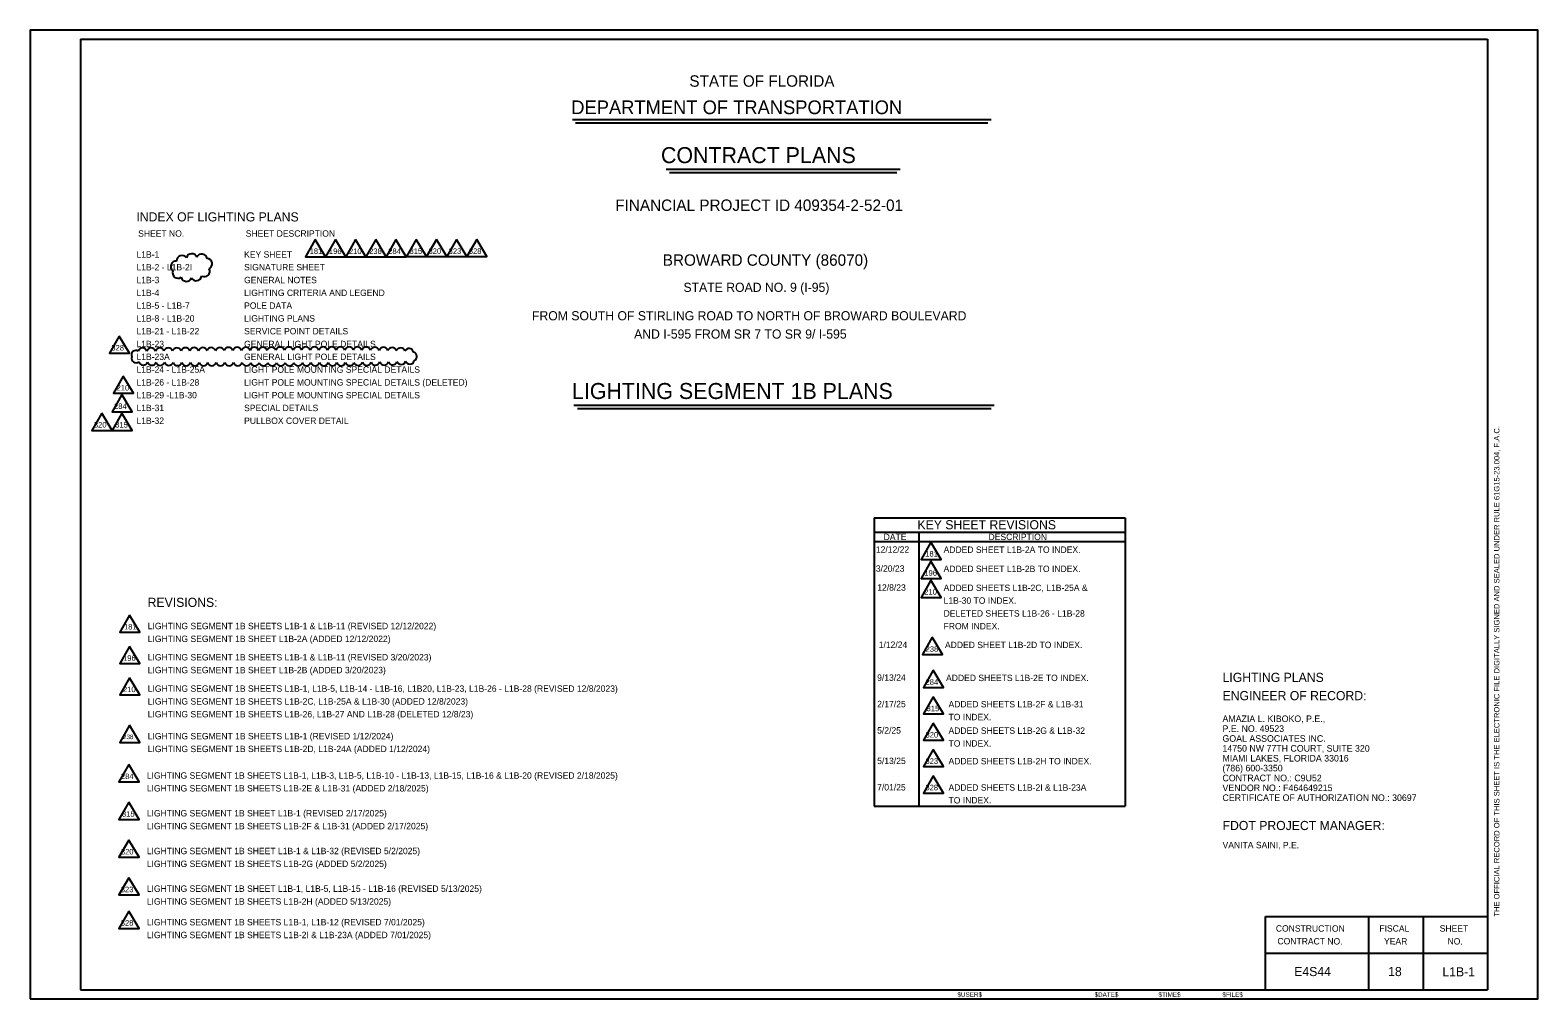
# Model space of a CAD drawing. Extents: x -818.6 to -802.1, y -2197.9 to -2175.
# Drawn here: x -818.56 to -802.06, y -2197.92 to -2187.32 of the extents above; entities that cross this region are included whole.
import ezdxf

# ---------------------------------------------------------------- set-up
doc = ezdxf.new("R2010")
doc.units = 0
for name, color, linetype in [('ActivePointCell_dp', 7, 'Continuous'), ('Cloud_dp', 7, 'Continuous'), ('PlotBorder_dp', 7, 'Continuous'), ('SheetBorder_dp', 7, 'Continuous'), ('SheetLines_dp', 7, 'Continuous'), ('SumBoxLines_dp', 7, 'Continuous'), ('TextLabel', 7, 'Continuous'), ('TextMinor', 7, 'Continuous'), ('TextMisc', 7, 'Continuous'), ('TextNotes', 7, 'Continuous'), ('TextShtNo', 7, 'Continuous'), ('TextTitle', 7, 'Continuous')]:
    doc.layers.add(name, color=color, linetype=linetype)

msp = doc.modelspace()

# ---------------------------------------------------------------- linework, layer by layer
at = {"layer": 'ActivePointCell_dp'}
msp.add_line((-802.614, -2187.419), (-802.614, -2187.419), dxfattribs=at)
at = {"layer": 'Cloud_dp'}
for points in [[(-815.443, -2189.61), (-815.551, -2189.798), (-815.33, -2189.798)], [(-815.222, -2189.61), (-815.33, -2189.798), (-815.109, -2189.798)], [(-815.002, -2189.61), (-815.109, -2189.798), (-814.889, -2189.798)], [(-814.781, -2189.61), (-814.889, -2189.798), (-814.668, -2189.798)], [(-814.56, -2189.61), (-814.667, -2189.798), (-814.447, -2189.798)], [(-814.339, -2189.609), (-814.446, -2189.797), (-814.226, -2189.797)], [(-814.118, -2189.609), (-814.226, -2189.797), (-814.005, -2189.797)], [(-813.897, -2189.609), (-814.005, -2189.797), (-813.784, -2189.797)], [(-813.677, -2189.609), (-813.784, -2189.797), (-813.564, -2189.797)], [(-817.588, -2190.666), (-817.696, -2190.854), (-817.475, -2190.854)], [(-817.545, -2191.104), (-817.652, -2191.292), (-817.432, -2191.292)], [(-817.559, -2191.306), (-817.667, -2191.494), (-817.446, -2191.494)], [(-817.78, -2191.509), (-817.888, -2191.698), (-817.667, -2191.698)], [(-817.559, -2191.509), (-817.667, -2191.698), (-817.446, -2191.698)], [(-808.706, -2192.922), (-808.814, -2193.11), (-808.593, -2193.11)], [(-808.706, -2193.13), (-808.814, -2193.318), (-808.593, -2193.318)], [(-808.706, -2193.338), (-808.814, -2193.526), (-808.593, -2193.526)], [(-817.475, -2193.719), (-817.583, -2193.907), (-817.362, -2193.907)], [(-808.691, -2193.963), (-808.799, -2194.151), (-808.578, -2194.151)], [(-817.475, -2194.062), (-817.583, -2194.25), (-817.362, -2194.25)], [(-808.68, -2194.324), (-808.787, -2194.512), (-808.567, -2194.512)], [(-817.475, -2194.405), (-817.583, -2194.593), (-817.362, -2194.593)], [(-808.68, -2194.613), (-808.787, -2194.801), (-808.567, -2194.801)], [(-817.475, -2194.924), (-817.583, -2195.113), (-817.362, -2195.113)], [(-808.68, -2194.901), (-808.787, -2195.089), (-808.567, -2195.089)], [(-808.68, -2195.19), (-808.787, -2195.378), (-808.567, -2195.378)], [(-817.485, -2195.356), (-817.593, -2195.544), (-817.372, -2195.544)], [(-808.68, -2195.478), (-808.787, -2195.667), (-808.567, -2195.667)], [(-817.485, -2195.768), (-817.593, -2195.957), (-817.372, -2195.957)], [(-817.485, -2196.181), (-817.593, -2196.369), (-817.372, -2196.369)], [(-817.485, -2196.594), (-817.593, -2196.782), (-817.372, -2196.782)], [(-817.485, -2196.96), (-817.593, -2197.148), (-817.372, -2197.148)]]:
    msp.add_lwpolyline(points, close=True, dxfattribs=at)
for centre, radius, start, end in [((-816.966, -2189.905), 0.0599, 86.9907, 231.9907), ((-816.902, -2189.845), 0.06, 35.4166, 180.4166), ((-816.795, -2189.825), 0.0599, 21.2778, 166.2778), ((-816.685, -2189.828), 0.0599, 9.9863, 154.9863), ((-816.632, -2189.877), 0.0599, 298.9542, 83.9542), ((-816.946, -2189.974), 0.0599, 159.4236, 304.4236), ((-816.854, -2190.008), 0.0599, 194.4381, 339.4381), ((-816.745, -2190.001), 0.0599, 207.5787, 352.5787), ((-816.657, -2189.957), 0.0599, 241.4449, 26.4449), ((-817.407, -2190.874), 0.0494, 58.9897, 203.9897), ((-817.334, -2190.846), 0.0494, 18.7741, 163.7741), ((-817.24, -2190.845), 0.0494, 17.5, 162.5), ((-817.146, -2190.845), 0.0494, 17.6778, 162.6778), ((-817.052, -2190.844), 0.0494, 17.8653, 162.8653), ((-816.958, -2190.844), 0.0494, 17.8653, 162.8653), ((-816.863, -2190.843), 0.0494, 17.8653, 162.8653), ((-816.769, -2190.842), 0.0494, 17.8653, 162.8653), ((-816.675, -2190.842), 0.0494, 17.8653, 162.8653), ((-816.581, -2190.841), 0.0494, 17.8653, 162.8653), ((-816.487, -2190.841), 0.0494, 17.8653, 162.8653), ((-816.393, -2190.84), 0.0494, 17.8653, 162.8653), ((-816.298, -2190.839), 0.0494, 17.8653, 162.8653), ((-816.204, -2190.839), 0.0494, 17.8653, 162.8653), ((-816.11, -2190.838), 0.0494, 17.8653, 162.8653), ((-816.016, -2190.838), 0.0494, 17.8653, 162.8653), ((-815.922, -2190.837), 0.0494, 17.8653, 162.8653), ((-815.828, -2190.836), 0.0494, 17.8653, 162.8653), ((-815.733, -2190.836), 0.0494, 17.8425, 162.8425), ((-815.639, -2190.835), 0.0494, 17.7853, 162.7853), ((-815.545, -2190.835), 0.0494, 17.7213, 162.7213), ((-815.451, -2190.835), 0.0494, 17.6494, 162.6494), ((-815.357, -2190.834), 0.0494, 17.5676, 162.5676), ((-815.263, -2190.834), 0.0494, 17.4736, 162.4736), ((-815.168, -2190.835), 0.0494, 17.3638, 162.3638), ((-815.074, -2190.835), 0.0494, 17.2336, 162.2336), ((-814.98, -2190.835), 0.0494, 17.0753, 162.0753), ((-814.886, -2190.836), 0.0494, 16.8775, 161.8775), ((-814.792, -2190.838), 0.0494, 16.6201, 161.6201), ((-814.698, -2190.839), 0.0494, 16.2655, 161.2655), ((-814.604, -2190.842), 0.0494, 15.7308, 160.7308), ((-814.51, -2190.845), 0.0494, 14.7785, 159.7785), ((-814.417, -2190.852), 0.0494, 12.0754, 157.0754), ((-814.38, -2190.89), 0.0493, 291.9354, 76.9354), ((-817.405, -2190.909), 0.0494, 163.0125, 308.0125), ((-817.327, -2190.935), 0.0494, 195.3369, 340.3369), ((-817.233, -2190.937), 0.0494, 196.5639, 341.5639), ((-817.139, -2190.939), 0.0494, 196.8661, 341.8661), ((-817.045, -2190.939), 0.0494, 197.0257, 342.0257), ((-816.951, -2190.94), 0.0494, 197.1286, 342.1286), ((-816.856, -2190.941), 0.0494, 197.2021, 342.2021), ((-816.762, -2190.941), 0.0494, 197.258, 342.258), ((-816.668, -2190.942), 0.0494, 197.3023, 342.3023), ((-816.574, -2190.942), 0.0494, 197.3386, 342.3386), ((-816.48, -2190.942), 0.0494, 197.369, 342.369), ((-816.386, -2190.942), 0.0494, 197.395, 342.395), ((-816.291, -2190.942), 0.0494, 197.4176, 342.4176), ((-816.197, -2190.943), 0.0494, 197.4374, 342.4374), ((-816.103, -2190.943), 0.0494, 197.4549, 342.4549), ((-816.009, -2190.943), 0.0494, 197.4706, 342.4706), ((-815.915, -2190.943), 0.0494, 197.4848, 342.4848), ((-815.821, -2190.943), 0.0494, 197.4992, 342.4992), ((-815.726, -2190.943), 0.0494, 197.5363, 342.5363), ((-815.632, -2190.943), 0.0494, 197.5851, 342.5851), ((-815.538, -2190.942), 0.0494, 197.6392, 342.6392), ((-815.444, -2190.942), 0.0494, 197.6998, 342.6998), ((-815.35, -2190.942), 0.0494, 197.7683, 342.7683), ((-815.256, -2190.941), 0.0494, 197.8466, 342.8466), ((-815.162, -2190.941), 0.0494, 197.9372, 342.9372), ((-815.067, -2190.94), 0.0494, 198.0438, 343.0438), ((-814.973, -2190.939), 0.0494, 198.1717, 343.1717), ((-814.879, -2190.938), 0.0494, 198.329, 343.329), ((-814.785, -2190.936), 0.0494, 198.5293, 343.5293), ((-814.691, -2190.934), 0.0494, 198.7965, 343.7965), ((-814.597, -2190.932), 0.0494, 199.1791, 344.1791), ((-814.503, -2190.928), 0.0494, 199.7957, 344.7957), ((-814.409, -2190.924), 0.0494, 201.074, 346.074)]:
    msp.add_arc(centre, radius, start, end, dxfattribs=at)
at = {"layer": 'PlotBorder_dp'}
msp.add_lwpolyline([(-818.564, -2197.919), (-802.064, -2197.919), (-802.064, -2187.319), (-818.564, -2187.319)], close=True, dxfattribs=at)
at = {"layer": 'SheetBorder_dp'}
for p, q in [((-818.014, -2187.419), (-818.014, -2197.819)), ((-818.014, -2187.419), (-802.614, -2187.419)), ((-802.614, -2187.419), (-802.614, -2197.819)), ((-818.014, -2197.819), (-802.614, -2197.819))]:
    msp.add_line(p, q, dxfattribs=at)
at = {"layer": 'SheetLines_dp'}
for p, q in [((-805.044, -2197.019), (-802.614, -2197.019)), ((-805.044, -2197.819), (-805.044, -2197.019)), ((-803.914, -2197.819), (-803.914, -2197.019)), ((-803.314, -2197.819), (-803.314, -2197.019)), ((-805.044, -2197.419), (-802.614, -2197.419))]:
    msp.add_line(p, q, dxfattribs=at)
at = {"layer": 'SumBoxLines_dp'}
for p, q in [((-809.327, -2192.654), (-809.327, -2195.812)), ((-809.327, -2192.654), (-806.58, -2192.654)), ((-806.58, -2192.654), (-806.58, -2195.812)), ((-809.327, -2192.814), (-806.58, -2192.814)), ((-808.837, -2192.814), (-808.837, -2195.812)), ((-809.327, -2192.914), (-806.58, -2192.914)), ((-809.327, -2195.812), (-806.58, -2195.812))]:
    msp.add_line(p, q, dxfattribs=at)
at = {"layer": 'TextTitle'}
for p, q in [((-812.63, -2188.295), (-808.048, -2188.295)), ((-812.597, -2188.333), (-808.083, -2188.333)), ((-811.605, -2188.84), (-809.044, -2188.84)), ((-811.566, -2188.878), (-809.077, -2188.878)), ((-812.614, -2191.421), (-808.015, -2191.421)), ((-812.575, -2191.459), (-808.047, -2191.459))]:
    msp.add_line(p, q, dxfattribs=at)

# ---------------------------------------------------------------- texts
at = {"layer": 'Cloud_dp'}
for s, height, p in [('181', 0.06, (-815.505, -2189.768)), ('196', 0.06, (-815.294, -2189.768)), ('210', 0.06, (-815.075, -2189.768)), ('238', 0.06, (-814.854, -2189.768)), ('284', 0.06, (-814.645, -2189.768)), ('315', 0.06, (-814.412, -2189.767)), ('320', 0.06, (-814.204, -2189.767)), ('323', 0.06, (-813.984, -2189.767)), ('328', 0.06, (-813.763, -2189.767)), ('328', 0.06, (-817.675, -2190.824)), ('210', 0.06, (-817.618, -2191.262)), ('284', 0.06, (-817.645, -2191.464)), ('320', 0.06, (-817.866, -2191.667)), ('315', 0.06, (-817.633, -2191.667)), ('181', 0.06, (-808.768, -2193.079)), ('196', 0.06, (-808.778, -2193.288)), ('210', 0.06, (-808.779, -2193.496)), ('181', 0.06, (-817.537, -2193.877)), ('196', 0.06, (-817.547, -2194.22)), ('238', 0.06, (-808.764, -2194.121)), ('284', 0.06, (-808.765, -2194.482)), ('210', 0.06, (-817.548, -2194.563)), ('315', 0.06, (-808.753, -2194.771)), ('238', 0.05, (-817.548, -2195.077)), ('320', 0.06, (-808.765, -2195.059)), ('323', 0.06, (-808.766, -2195.348)), ('284', 0.06, (-817.57, -2195.514)), ('328', 0.06, (-808.766, -2195.636)), ('315', 0.06, (-817.559, -2195.926)), ('320', 0.06, (-817.571, -2196.339)), ('323', 0.06, (-817.572, -2196.752)), ('328', 0.06, (-817.572, -2197.118))]:
    msp.add_text(s, height=height, rotation=0, dxfattribs=at).set_placement(p)
at = {"layer": 'TextLabel'}
for s, height, p in [('FINANCIAL PROJECT ID 409354-2-52-01', 0.125, (-812.16, -2189.297)), ('INDEX OF LIGHTING PLANS', 0.1, (-817.401, -2189.412)), ('L1B-1', 0.07, (-817.4, -2189.808)), ('L1B-2 - L1B-2I', 0.07, (-817.4, -2189.948)), ('SIGNATURE SHEET', 0.07, (-816.222, -2189.948)), ('KEY SHEET', 0.07, (-816.222, -2189.808)), ('BROWARD COUNTY (86070)', 0.125, (-811.64, -2189.897)), ('L1B-3', 0.07, (-817.4, -2190.088)), ('GENERAL NOTES', 0.07, (-816.222, -2190.088)), ('L1B-4', 0.07, (-817.4, -2190.228)), ('LIGHTING CRITERIA AND LEGEND', 0.07, (-816.222, -2190.228)), ('STATE ROAD NO. 9 (I-95)', 0.1, (-811.414, -2190.183)), ('L1B-5 - L1B-7', 0.07, (-817.4, -2190.368)), ('POLE DATA', 0.07, (-816.222, -2190.368)), ('L1B-8 - L1B-20', 0.07, (-817.4, -2190.508)), ('LIGHTING PLANS', 0.07, (-816.222, -2190.508)), ('FROM SOUTH OF STIRLING ROAD TO NORTH OF BROWARD BOULEVARD', 0.1, (-813.072, -2190.494)), ('L1B-21 - L1B-22', 0.07, (-817.4, -2190.648)), ('SERVICE POINT DETAILS', 0.07, (-816.222, -2190.648)), ('AND I-595 FROM SR 7 TO SR 9/ I-595', 0.1, (-811.954, -2190.694)), ('L1B-23', 0.07, (-817.4, -2190.788)), ('L1B-23A', 0.07, (-817.4, -2190.928)), ('GENERAL LIGHT POLE DETAILS', 0.07, (-816.222, -2190.788)), ('GENERAL LIGHT POLE DETAILS', 0.07, (-816.222, -2190.928)), ('L1B-24 - L1B-25A', 0.07, (-817.4, -2191.068)), ('LIGHT POLE MOUNTING SPECIAL DETAILS', 0.07, (-816.222, -2191.068)), ('L1B-26 - L1B-28', 0.07, (-817.4, -2191.208)), ('LIGHT POLE MOUNTING SPECIAL DETAILS (DELETED)', 0.07, (-816.222, -2191.208)), ('L1B-29 -L1B-30', 0.07, (-817.4, -2191.348)), ('LIGHT POLE MOUNTING SPECIAL DETAILS', 0.07, (-816.222, -2191.348)), ('L1B-31', 0.07, (-817.4, -2191.488)), ('SPECIAL DETAILS', 0.07, (-816.222, -2191.488)), ('L1B-32', 0.07, (-817.4, -2191.628)), ('PULLBOX COVER DETAIL', 0.07, (-816.222, -2191.628)), ('KEY SHEET REVISIONS', 0.1, (-808.853, -2192.781)), ('REVISIONS:', 0.1, (-817.278, -2193.63)), ('LIGHTING PLANS', 0.1, (-805.514, -2194.451)), ('ENGINEER OF RECORD:', 0.1, (-805.514, -2194.651)), ('AMAZIA L. KIBOKO, P.E.,', 0.07202, (-805.515, -2194.89)), ('P.E. NO. 49523', 0.07202, (-805.515, -2194.998)), ('GOAL ASSOCIATES INC. ', 0.07202, (-805.515, -2195.106)), ('14750 NW 77TH COURT, SUITE 320', 0.07202, (-805.515, -2195.214)), ('MIAMI LAKES, FLORIDA 33016', 0.07202, (-805.515, -2195.322)), ('CONTRACT NO.: C9U52', 0.07202, (-805.515, -2195.538)), ('(786) 600-3350', 0.07202, (-805.515, -2195.43)), ('VENDOR NO.: F464649215', 0.07202, (-805.515, -2195.646)), ('CERTIFICATE OF AUTHORIZATION NO.: 30697', 0.07202, (-805.515, -2195.754)), ('E4S44', 0.1, (-804.73, -2197.67)), ('18', 0.1, (-803.702, -2197.67))]:
    msp.add_text(s, height=height, dxfattribs=at).set_placement(p)
at = {"layer": 'TextMinor'}
for s, height, p in [('12/12/22', 0.07, (-809.308, -2193.037)), ('ADDED SHEET L1B-2A TO INDEX.', 0.07, (-808.567, -2193.039)), ('3/20/23', 0.07, (-809.308, -2193.245)), ('ADDED SHEET L1B-2B TO INDEX.', 0.07, (-808.567, -2193.248)), ('12/8/23', 0.07, (-809.293, -2193.453)), ('ADDED SHEETS L1B-2C, L1B-25A & ', 0.07, (-808.567, -2193.456)), ('L1B-30 TO INDEX.', 0.07, (-808.567, -2193.596)), ('DELETED SHEETS L1B-26 - L1B-28 ', 0.07, (-808.567, -2193.736)), ('FROM INDEX.', 0.07, (-808.567, -2193.876)), ('1/12/24', 0.07, (-809.277, -2194.079)), ('ADDED SHEET L1B-2D TO INDEX.', 0.07, (-808.552, -2194.081)), ('9/13/24', 0.07, (-809.294, -2194.439)), ('ADDED SHEETS L1B-2E TO INDEX.', 0.07, (-808.54, -2194.442)), ('2/17/25', 0.07, (-809.294, -2194.728)), ('ADDED SHEETS L1B-2F & L1B-31      ', 0.07, (-808.513, -2194.73)), ('TO INDEX.', 0.07, (-808.513, -2194.87)), ('5/2/25', 0.07, (-809.294, -2195.016)), ('ADDED SHEETS L1B-2G & L1B-32      ', 0.07, (-808.513, -2195.019)), ('TO INDEX.', 0.07, (-808.513, -2195.159)), ('5/13/25', 0.07, (-809.294, -2195.35)), ('ADDED SHEETS L1B-2H TO INDEX.', 0.07, (-808.513, -2195.353)), ('7/01/25', 0.07, (-809.294, -2195.639)), ('ADDED SHEETS L1B-2I & L1B-23A ', 0.07, (-808.513, -2195.641)), ('TO INDEX.', 0.07, (-808.513, -2195.781)), ('$USER$', 0.05, (-808.415, -2197.897))]:
    msp.add_text(s, height=height, dxfattribs=at).set_placement(p)
for s, p in [('$DATE$', (-806.915, -2197.897)), ('$TIME$', (-806.215, -2197.897)), ('$FILE$', (-805.515, -2197.897))]:
    msp.add_text(s, height=0.05, rotation=360, dxfattribs=at).set_placement(p)
at = {"layer": 'TextMisc'}
msp.add_text('THE OFFICIAL RECORD OF THIS SHEET IS THE ELECTRONIC FILE DIGITALLY SIGNED AND SEALED UNDER RULE 61G15-23.004, F.A.C.', height=0.06, rotation=90, dxfattribs=at).set_placement((-802.484, -2197.019))
at = {"layer": 'TextNotes'}
for s, height, p in [('SHEET NO.', 0.07, (-817.382, -2189.579)), ('SHEET DESCRIPTION', 0.07, (-816.204, -2189.579)), ('DATE', 0.07, (-809.223, -2192.899)), ('DESCRIPTION', 0.07, (-808.075, -2192.899)), ('LIGHTING SEGMENT 1B SHEETS L1B-1 & L1B-11 (REVISED 12/12/2022)', 0.06998, (-817.277, -2193.874)), ('LIGHTING SEGMENT 1B SHEET L1B-2A (ADDED 12/12/2022)', 0.06998, (-817.277, -2194.014)), ('LIGHTING SEGMENT 1B SHEETS L1B-1 & L1B-11 (REVISED 3/20/2023)', 0.06998, (-817.277, -2194.216)), ('LIGHTING SEGMENT 1B SHEET L1B-2B (ADDED 3/20/2023)', 0.06998, (-817.277, -2194.356)), ('LIGHTING SEGMENT 1B SHEETS L1B-1, L1B-5, L1B-14 - L1B-16, L1B20, L1B-23, L1B-26 - L1B-28 (REVISED 12/8/2023)', 0.069982, (-817.277, -2194.559)), ('LIGHTING SEGMENT 1B SHEETS L1B-2C, L1B-25A & L1B-30 (ADDED 12/8/2023)', 0.06998, (-817.277, -2194.699)), ('LIGHTING SEGMENT 1B SHEETS L1B-26, L1B-27 AND L1B-28 (DELETED 12/8/23)', 0.06998, (-817.277, -2194.839)), ('LIGHTING SEGMENT 1B SHEETS L1B-1 (REVISED 1/12/2024)', 0.06998, (-817.277, -2195.079)), ('LIGHTING SEGMENT 1B SHEETS L1B-2D, L1B-24A (ADDED 1/12/2024)', 0.06998, (-817.277, -2195.219)), ('LIGHTING SEGMENT 1B SHEETS L1B-1, L1B-3, L1B-5, L1B-10 - L1B-13, L1B-15, L1B-16 & L1B-20 (REVISED 2/18/2025)', 0.069982, (-817.287, -2195.51)), ('LIGHTING SEGMENT 1B SHEETS L1B-2E & L1B-31 (ADDED 2/18/2025)', 0.06998, (-817.287, -2195.65)), ('LIGHTING SEGMENT 1B SHEET L1B-1 (REVISED 2/17/2025)', 0.06998, (-817.287, -2195.923)), ('FDOT PROJECT MANAGER:', 0.1, (-805.514, -2196.072)), ('LIGHTING SEGMENT 1B SHEETS L1B-2F & L1B-31 (ADDED 2/17/2025)', 0.06998, (-817.287, -2196.063)), ('LIGHTING SEGMENT 1B SHEET L1B-1 & L1B-32 (REVISED 5/2/2025)', 0.06998, (-817.287, -2196.336)), ('VANITA SAINI, P.E.', 0.07, (-805.514, -2196.271)), ('LIGHTING SEGMENT 1B SHEETS L1B-2G (ADDED 5/2/2025)', 0.06998, (-817.287, -2196.476)), ('LIGHTING SEGMENT 1B SHEET L1B-1, L1B-5, L1B-15 - L1B-16 (REVISED 5/13/2025)', 0.06998, (-817.287, -2196.748)), ('LIGHTING SEGMENT 1B SHEETS L1B-2H (ADDED 5/13/2025)', 0.06998, (-817.287, -2196.888)), ('LIGHTING SEGMENT 1B SHEETS L1B-1, L1B-12 (REVISED 7/01/2025)', 0.06998, (-817.287, -2197.115)), ('LIGHTING SEGMENT 1B SHEETS L1B-2I & L1B-23A (ADDED 7/01/2025)', 0.06998, (-817.287, -2197.255))]:
    msp.add_text(s, height=height, dxfattribs=at).set_placement(p)
for s, p in [('CONSTRUCTION', (-804.931, -2197.183)), ('FISCAL', (-803.798, -2197.183)), ('SHEET', (-803.138, -2197.183)), ('CONTRACT NO.', (-804.913, -2197.323)), ('YEAR', (-803.747, -2197.324)), ('NO.', (-803.052, -2197.324))]:
    msp.add_text(s, height=0.07, rotation=359.8607, dxfattribs=at).set_placement(p)
at = {"layer": 'TextShtNo'}
msp.add_text('L1B-1', height=0.1, dxfattribs=at).set_placement((-803.108, -2197.673))
at = {"layer": 'TextTitle'}
for s, height, p in [('STATE OF FLORIDA', 0.125, (-811.349, -2187.938)), ('DEPARTMENT OF TRANSPORTATION', 0.15, (-812.642, -2188.238)), ('CONTRACT PLANS', 0.175, (-811.66, -2188.774)), ('LIGHTING SEGMENT 1B PLANS', 0.175, (-812.634, -2191.355))]:
    msp.add_text(s, height=height, dxfattribs=at).set_placement(p)

doc.saveas('drawing.dxf')
